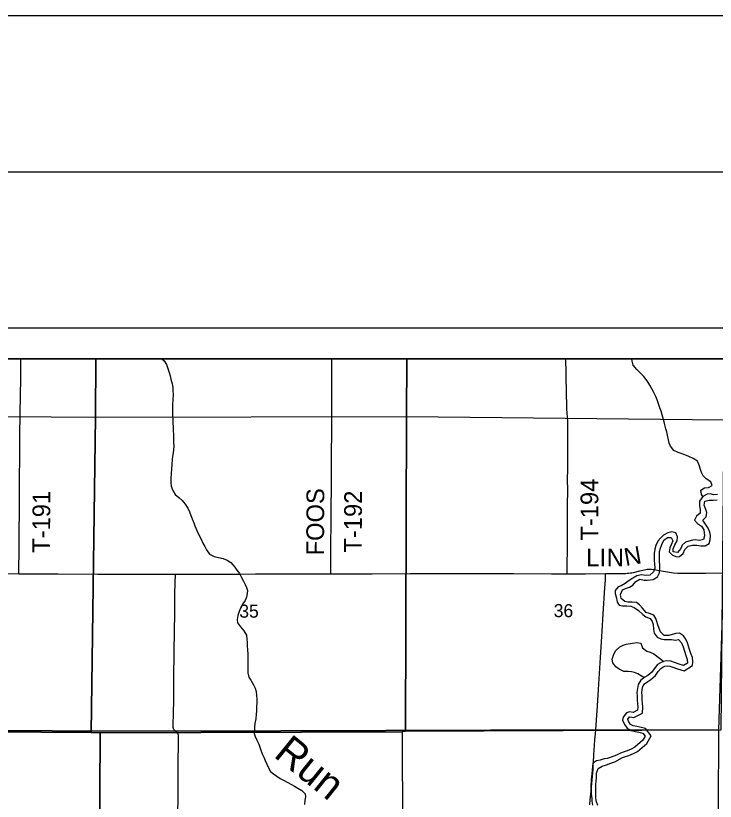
# Model space of a CAD drawing. Extents: x 0 to 45.9, y 0 to 22.
# Drawn here: x 3.224 to 5.466, y 19.483 to 22 of the extents above; entities that cross this region are included whole.
import ezdxf

# ---------------------------------------------------------------- set-up
doc = ezdxf.new("R2010")
doc.units = 0
for name, color, linetype in [('Default', 7, 'Continuous'), ('GM_X_County_Road', 7, 'Continuous'), ('GM_X_County_Road_Text', 7, 'Continuous'), ('GM_X_Major_River', 7, 'Continuous'), ('GM_X_Minor_River', 7, 'Continuous'), ('GM_X_Minor_River_Text', 7, 'Continuous'), ('GM_X_Section', 7, 'Continuous'), ('GM_X_Section_Text', 7, 'Continuous'), ('GM_X_Township_Road', 7, 'Continuous'), ('GM_X_Township_Road_Text', 7, 'Continuous'), ('SH_Cut_Line', 7, 'Continuous'), ('SH_Data', 7, 'Continuous'), ('SH_Text', 7, 'Continuous')]:
    doc.layers.add(name, color=color, linetype=linetype)

msp = doc.modelspace()

# ---------------------------------------------------------------- linework, layer by layer
at = {"layer": 'Default'}
for points in [[(5.5025, 20.9), (2.1, 20.9), (2.1, 19.7114), (2.15, 19.7113), (3.7367, 19.7072), (5.0826, 19.712), (5.4773, 19.7108), (5.4937, 20.2154)], [(3.4805, 20.9), (2.4813, 20.9), (2.4804, 20.7206), (3.4792, 20.7133)], [(4.477, 20.9), (3.4805, 20.9), (3.4792, 20.7133), (4.4764, 20.7161)], [(5.4943, 20.9), (4.477, 20.9), (4.4764, 20.7161), (5.4933, 20.7051)], [(2.1, 19.7114), (2.1, 14.1), (5.4538, 14.1), (5.4606, 15.6588), (5.4651, 16.7018), (5.4694, 17.7061), (5.4802, 18.3214), (5.4737, 18.7216), (5.4752, 19.0482), (5.4759, 19.2109), (5.4773, 19.7108), (5.0826, 19.712), (3.7367, 19.7072), (2.15, 19.7113)]]:
    msp.add_lwpolyline(points, close=True, dxfattribs=at)
at = {"layer": 'GM_X_County_Road'}
for points in [[(2.2656, 20.2142), (2.3, 20.2144), (2.3995, 20.2148), (2.4461, 20.2148), (2.5274, 20.2146), (2.617, 20.2142), (2.7134, 20.2139), (2.7506, 20.2139), (2.8874, 20.2128), (2.962, 20.2127), (3.0987, 20.2123), (3.2334, 20.2117)], [(5.1146, 20.2123), (5.1219, 20.2124), (5.1549, 20.2128), (5.171, 20.213), (5.1779, 20.213), (5.1838, 20.2134), (5.1894, 20.2138), (5.1946, 20.2143), (5.1986, 20.215), (5.204, 20.216), (5.2239, 20.2209), (5.2388, 20.2248), (5.2438, 20.2259), (5.2481, 20.2264), (5.253, 20.2266), (5.2573, 20.2264), (5.2622, 20.226), (5.2694, 20.2251), (5.2757, 20.2243), (5.2858, 20.2227), (5.2999, 20.2202), (5.3194, 20.2165), (5.3259, 20.2155), (5.3324, 20.2148), (5.3463, 20.2139), (5.3569, 20.2137), (5.4364, 20.214), (5.4929, 20.2148)], [(3.2334, 20.2117), (3.2572, 20.2116), (3.3598, 20.2112), (3.4872, 20.2108), (3.5866, 20.2106), (3.711, 20.2109), (3.7356, 20.2109)], [(3.7356, 20.2109), (3.8228, 20.2108), (3.944, 20.2108), (3.992, 20.2111), (4.1119, 20.2116), (4.2144, 20.2116), (4.2337, 20.2116)], [(4.2337, 20.2116), (4.2766, 20.2117), (4.3667, 20.212), (4.4879, 20.2121), (4.6246, 20.2122), (4.6837, 20.2122), (4.8205, 20.2121), (4.9416, 20.2119), (4.9918, 20.2119)], [(4.9918, 20.2119), (5.0504, 20.2119), (5.1146, 20.2123)], [(5.0828, 19.7114), (5.085, 19.7422), (5.0883, 19.7887), (5.0919, 19.8413), (5.0985, 19.9436), (5.1018, 19.9932), (5.1039, 20.0273), (5.1071, 20.0831), (5.1125, 20.1668), (5.1139, 20.1914), (5.1142, 20.1993), (5.1145, 20.2092), (5.1146, 20.2123)], [(5.0636, 19.4717), (5.0655, 19.4888), (5.0671, 19.5049), (5.0698, 19.5293), (5.0717, 19.5509), (5.0737, 19.5725), (5.0745, 19.583), (5.0748, 19.5898), (5.0752, 19.6), (5.0755, 19.6065), (5.077, 19.632), (5.0789, 19.6618), (5.0804, 19.6804), (5.0819, 19.6989), (5.0828, 19.7114)]]:
    msp.add_lwpolyline(points, dxfattribs=at)
at = {"layer": 'GM_X_Major_River'}
for points in [[(5.4738, 20.4657), (5.4613, 20.4648), (5.4496, 20.4681), (5.4401, 20.4668), (5.4263, 20.4591), (5.4158, 20.4449), (5.4151, 20.4305), (5.4175, 20.4171), (5.418, 20.4061), (5.4064, 20.3961), (5.4001, 20.3833), (5.4094, 20.3728), (5.4221, 20.3646), (5.429, 20.3523), (5.4311, 20.3424), (5.4312, 20.3329), (5.4283, 20.3216), (5.4154, 20.3188), (5.4022, 20.3202), (5.3927, 20.3193), (5.3809, 20.3165), (5.371, 20.3129), (5.3598, 20.3029), (5.3554, 20.2923), (5.3449, 20.28), (5.3317, 20.2822), (5.3312, 20.2921), (5.3367, 20.3041), (5.3438, 20.3172), (5.3452, 20.3297), (5.3402, 20.3428), (5.3274, 20.3457), (5.3137, 20.3429), (5.3007, 20.3356), (5.2906, 20.3259), (5.2825, 20.3159), (5.2754, 20.3023), (5.2721, 20.291), (5.2699, 20.2762), (5.27, 20.2664), (5.2705, 20.2538), (5.2715, 20.2439), (5.2723, 20.2302), (5.2683, 20.2178), (5.2567, 20.207), (5.2438, 20.2062), (5.2295, 20.2087), (5.215, 20.2052), (5.2016, 20.1975), (5.1901, 20.1906), (5.177, 20.1806), (5.1643, 20.1732), (5.1544, 20.1697), (5.1455, 20.1577), (5.1449, 20.1482), (5.1491, 20.1333), (5.1519, 20.1203), (5.1585, 20.1107), (5.169, 20.109), (5.1823, 20.1091), (5.1955, 20.108), (5.2064, 20.104), (5.2198, 20.0939), (5.2336, 20.081), (5.244, 20.074), (5.2572, 20.0684), (5.2641, 20.0584), (5.2666, 20.0488), (5.2678, 20.034), (5.2702, 20.0218), (5.2798, 20.009), (5.2921, 20.0031), (5.3023, 20.0014), (5.3125, 20.0011), (5.3262, 20.0016), (5.3386, 19.9995), (5.3485, 20.0012), (5.3581, 19.9899), (5.3635, 19.9777), (5.3674, 19.9632), (5.3717, 19.9498)], [(5.352, 20.0216), (5.3402, 20.0207), (5.328, 20.0168), (5.3173, 20.0136), (5.3026, 20.0143), (5.2903, 20.0255), (5.286, 20.0359), (5.2821, 20.0485), (5.2785, 20.0584), (5.2753, 20.068), (5.2687, 20.0788), (5.2549, 20.0848), (5.2451, 20.088), (5.2332, 20.1012), (5.2233, 20.112), (5.2132, 20.1198), (5.2, 20.1212), (5.1863, 20.1208), (5.1758, 20.1229), (5.165, 20.1322), (5.1622, 20.1456), (5.1686, 20.1599), (5.1789, 20.165), (5.1908, 20.1693), (5.2015, 20.1755), (5.2116, 20.1875), (5.2239, 20.1944), (5.2382, 20.1915), (5.248, 20.1909), (5.2575, 20.1918), (5.2674, 20.1939), (5.2812, 20.2023), (5.2879, 20.2151), (5.2889, 20.2276), (5.2881, 20.2402), (5.2875, 20.2504), (5.287, 20.2599), (5.2869, 20.2732), (5.2878, 20.2827), (5.2903, 20.2933), (5.2944, 20.3057), (5.3014, 20.3189), (5.3126, 20.3278), (5.3251, 20.3283), (5.3306, 20.3168), (5.3246, 20.3047), (5.3202, 20.2946), (5.3188, 20.2817), (5.3292, 20.2716), (5.3427, 20.2656), (5.3515, 20.2666), (5.363, 20.277), (5.369, 20.2898), (5.3798, 20.3002), (5.3931, 20.3033), (5.4068, 20.3034), (5.4203, 20.3008), (5.4343, 20.3009), (5.4466, 20.3086), (5.4499, 20.3207), (5.4506, 20.3348), (5.4485, 20.3447), (5.4439, 20.3581), (5.4351, 20.3708), (5.4259, 20.3835), (5.4367, 20.3947), (5.4393, 20.4079), (5.4364, 20.4175), (5.4311, 20.432), (5.4332, 20.4449), (5.4469, 20.4473), (5.4598, 20.4478), (5.4723, 20.4486)], [(5.393, 19.9182), (5.3944, 19.9307), (5.3931, 19.9429), (5.3881, 19.9563), (5.3834, 19.9689), (5.3799, 19.98), (5.3771, 19.9899), (5.3716, 20.0026), (5.3643, 20.0126), (5.352, 20.0216)], [(5.3717, 19.9498), (5.3759, 19.9372), (5.3768, 19.9257), (5.3638, 19.9177), (5.3502, 19.9217), (5.336, 19.9277), (5.3232, 19.9318), (5.3103, 19.9328), (5.3001, 19.9304), (5.2905, 19.9264), (5.2805, 19.9205), (5.2704, 19.9075), (5.263, 19.8966), (5.2503, 19.8858), (5.2407, 19.88), (5.2276, 19.8704), (5.2194, 19.8565), (5.2165, 19.844), (5.215, 19.8308), (5.2156, 19.8209), (5.2161, 19.8079), (5.2173, 19.7946), (5.2179, 19.7851), (5.2173, 19.7749), (5.2027, 19.7676), (5.1914, 19.7697), (5.1819, 19.7665), (5.171, 19.7527), (5.1693, 19.7428), (5.1754, 19.729), (5.1839, 19.7171), (5.1966, 19.7096), (5.2109, 19.7063), (5.2211, 19.7042), (5.2335, 19.7012), (5.2416, 19.6912), (5.2342, 19.6781), (5.2079, 19.6558), (5.1968, 19.65), (5.1835, 19.6442), (5.1739, 19.6413), (5.1625, 19.6374), (5.1491, 19.6305), (5.1323, 19.6244), (5.1197, 19.6201), (5.1102, 19.6184), (5.0973, 19.6145), (5.0855, 19.612), (5.074, 19.6047), (5.0722, 19.5945), (5.0712, 19.5823), (5.0702, 19.5713), (5.0689, 19.5607), (5.0679, 19.5513), (5.0675, 19.5296), (5.068, 19.5182), (5.0688, 19.5049), (5.0705, 19.4931), (5.0707, 19.4832), (5.0727, 19.4706)], [(5.1437, 19.6093), (5.1688, 19.6227), (5.1788, 19.6262), (5.1889, 19.6292), (5.2037, 19.6356), (5.2169, 19.6425), (5.2466, 19.6677), (5.2608, 19.6928), (5.2425, 19.7155), (5.2245, 19.7197), (5.2143, 19.7218), (5.2026, 19.7246), (5.1949, 19.7291), (5.1893, 19.7369), (5.1858, 19.7449), (5.186, 19.746), (5.1915, 19.7529), (5.1926, 19.7533), (5.2051, 19.751), (5.2326, 19.7648), (5.2338, 19.7851), (5.2332, 19.7958), (5.232, 19.809), (5.2315, 19.8216), (5.231, 19.8303), (5.2322, 19.8414), (5.2343, 19.8505), (5.2396, 19.8595), (5.2496, 19.8668), (5.2596, 19.8729), (5.2749, 19.8858), (5.2833, 19.8981), (5.2913, 19.9084), (5.2976, 19.9121), (5.305, 19.9152), (5.3116, 19.9168), (5.3201, 19.9161), (5.3305, 19.9128), (5.3449, 19.9067), (5.3661, 19.9004), (5.393, 19.9182)], [(5.0897, 19.4695), (5.0847, 19.4844), (5.0834, 19.497), (5.0833, 19.5069), (5.0831, 19.5164), (5.0833, 19.5263), (5.0835, 19.5357), (5.0841, 19.5483), (5.0851, 19.5581), (5.0858, 19.5729), (5.0906, 19.5876), (5.1041, 19.5957), (5.1174, 19.6), (5.1319, 19.605), (5.1437, 19.6093)]]:
    msp.add_lwpolyline(points, dxfattribs=at)
at = {"layer": 'GM_X_Minor_River'}
for points in [[(3.6925, 20.9), (3.6995, 20.8943), (3.7076, 20.8827), (3.7108, 20.8724), (3.7157, 20.8571), (3.7189, 20.846), (3.7213, 20.8353), (3.7252, 20.8201), (3.7272, 20.8094), (3.7278, 20.7999), (3.7282, 20.7855), (3.7272, 20.7703), (3.726, 20.7536), (3.7258, 20.7422), (3.726, 20.7312), (3.7261, 20.7205), (3.7272, 20.7027), (3.7274, 20.6932), (3.728, 20.6837), (3.7288, 20.6704), (3.729, 20.6582), (3.7295, 20.6468), (3.7299, 20.6327), (3.7301, 20.621), (3.7291, 20.6092), (3.7281, 20.5997), (3.7263, 20.588), (3.7254, 20.5778), (3.7243, 20.5634), (3.7228, 20.5471), (3.7218, 20.5334), (3.7211, 20.5186), (3.7208, 20.5034), (3.722, 20.492), (3.7271, 20.479), (3.7351, 20.4655), (3.7467, 20.4562), (3.7571, 20.4468), (3.767, 20.4352), (3.7755, 20.4218), (3.7809, 20.4099), (3.7852, 20.3988), (3.7891, 20.3877), (3.7942, 20.375), (3.7978, 20.3655), (3.8039, 20.3509), (3.8093, 20.3386)], [(5.4263, 20.4591), (5.4223, 20.4656), (5.4203, 20.4801), (5.4318, 20.4875), (5.4447, 20.4887), (5.4566, 20.4942), (5.4519, 20.506), (5.437, 20.5162), (5.4277, 20.5259), (5.4223, 20.5363), (5.4187, 20.5458), (5.4144, 20.56), (5.4094, 20.5726), (5.3956, 20.5809), (5.3813, 20.5873), (5.3689, 20.5928), (5.3573, 20.5969), (5.3471, 20.6001), (5.3336, 20.6065), (5.3222, 20.6208), (5.3186, 20.6307), (5.3166, 20.6414), (5.3135, 20.6555), (5.3107, 20.6662), (5.3079, 20.6765), (5.3047, 20.6891), (5.3023, 20.699), (5.2955, 20.7208), (5.2924, 20.7327), (5.2888, 20.743), (5.2842, 20.7568), (5.2795, 20.7686), (5.2752, 20.7801), (5.2694, 20.7928), (5.2632, 20.8047), (5.2567, 20.8162), (5.2475, 20.8301), (5.2376, 20.8443), (5.2246, 20.8571), (5.2149, 20.8661), (5.2035, 20.8804), (5.1996, 20.8934), (5.1985, 20.9)], [(3.8093, 20.3386), (3.8177, 20.3221), (3.8238, 20.3102), (3.8304, 20.2987), (3.8355, 20.2887), (3.8451, 20.2748), (3.86, 20.2666), (3.874, 20.264), (3.8883, 20.2607), (3.9015, 20.2554), (3.9138, 20.248), (3.926, 20.2333), (3.933, 20.2233), (3.9411, 20.2125), (3.9476, 20.1998), (3.9542, 20.1879), (3.9592, 20.1771), (3.9632, 20.1676), (3.9664, 20.158), (3.9658, 20.1481), (3.9633, 20.1372), (3.9593, 20.1262), (3.9507, 20.1139), (3.9448, 20.1011), (3.9404, 20.0906), (3.9356, 20.0777), (3.9334, 20.0653), (3.9351, 20.055), (3.9446, 20.0415), (3.9554, 20.0291), (3.963, 20.0153), (3.965, 20.0019), (3.9655, 19.9913), (3.9657, 19.9803), (3.9666, 19.9677), (3.9674, 19.954), (3.9675, 19.9415), (3.9676, 19.9271), (3.9674, 19.9168), (3.9679, 19.9058), (3.968, 19.894), (3.9712, 19.8803), (3.9778, 19.8706), (3.9858, 19.856), (3.9912, 19.8453), (3.9948, 19.835), (3.996, 19.8216), (3.9962, 19.811), (3.9964, 19.8004), (3.9957, 19.7848), (3.9954, 19.7715), (3.9948, 19.7617), (3.993, 19.7469), (3.9907, 19.7317), (3.9894, 19.72), (3.9888, 19.7098), (3.9886, 19.6999), (3.991, 19.69), (3.9964, 19.6785), (4.0026, 19.6658), (4.008, 19.6501), (4.0133, 19.6352), (4.0188, 19.6244), (4.0235, 19.6129), (4.0285, 19.6014), (4.0332, 19.5915), (4.0409, 19.5784), (4.0506, 19.5702), (4.0607, 19.5636), (4.0719, 19.5561), (4.0846, 19.549), (4.0943, 19.5435), (4.1074, 19.5364), (4.1175, 19.5316), (4.1276, 19.5246), (4.1411, 19.5174), (4.1518, 19.507), (4.1524, 19.4971), (4.151, 19.4865), (4.1496, 19.4724)], [(5.2392, 19.8789), (5.2317, 19.8821), (5.2182, 19.8915), (5.2073, 19.8955), (5.1975, 19.8976), (5.1877, 19.8982), (5.1726, 19.8989), (5.1576, 19.9064), (5.1479, 19.9138), (5.1379, 19.9262), (5.1359, 19.938), (5.1415, 19.9542), (5.1479, 19.9662), (5.1602, 19.9774), (5.1705, 19.9828), (5.1808, 19.9857), (5.2013, 19.989), (5.2143, 19.9918), (5.2271, 19.9893), (5.2332, 19.9747), (5.247, 19.9642), (5.2575, 19.9601), (5.2692, 19.9557), (5.3011, 19.9306)]]:
    msp.add_lwpolyline(points, dxfattribs=at)
at = {"layer": 'GM_X_Section'}
for points in [[(2.4804, 20.7206), (3.4792, 20.7133), (3.4656, 19.7033), (2.5108, 19.7095), (2.4582, 19.7121)], [(3.4792, 20.7133), (4.4764, 20.7161), (4.4734, 19.7064), (4.4624, 19.7057), (3.494, 19.7024), (3.4656, 19.7033)], [(4.4764, 20.7161), (5.4933, 20.7051), (5.4839, 19.711), (4.4734, 19.7064)], [(2.5108, 19.7095), (3.4656, 19.7033), (3.494, 19.7024), (3.4889, 18.7329), (2.5019, 18.7014)], [(3.494, 19.7024), (4.4624, 19.7057), (4.4658, 18.7509), (3.4889, 18.7329)]]:
    msp.add_lwpolyline(points, close=True, dxfattribs=at)
at = {"layer": 'GM_X_Township_Road'}
for points in [[(3.2334, 20.2117), (3.2335, 20.2148), (3.2343, 20.2967), (3.235, 20.3432), (3.2356, 20.4147), (3.2357, 20.4519), (3.236, 20.4861), (3.2361, 20.5296), (3.2367, 20.5731), (3.2374, 20.6476), (3.2384, 20.7315), (3.2391, 20.7781), (3.2399, 20.8433), (3.2403, 20.8774), (3.2406, 20.9)], [(4.2337, 20.2116), (4.2338, 20.2146), (4.234, 20.2212), (4.2341, 20.3051), (4.2344, 20.3734), (4.2349, 20.4262), (4.2358, 20.4852), (4.2359, 20.5163), (4.2361, 20.566), (4.2363, 20.6126), (4.2368, 20.6499), (4.237, 20.6716), (4.2372, 20.7493), (4.2373, 20.7927), (4.2372, 20.8145), (4.2374, 20.8393), (4.2368, 20.9)], [(4.9918, 20.2119), (4.9918, 20.2156), (4.9918, 20.2258), (4.9919, 20.2333), (4.9924, 20.2985), (4.9925, 20.3296), (4.9928, 20.398), (4.9928, 20.4135), (4.993, 20.4477), (4.9931, 20.4632), (4.9933, 20.4849), (4.9929, 20.5099), (4.9933, 20.551), (4.9937, 20.5922), (4.9938, 20.6134), (4.994, 20.6474), (4.994, 20.6557), (4.9936, 20.675), (4.9931, 20.6992), (4.9907, 20.7402), (4.99, 20.7582), (4.9892, 20.783), (4.9881, 20.8545), (4.9874, 20.9)], [(3.7296, 19.7151), (3.7292, 19.7161), (3.7284, 19.7191), (3.7281, 19.7222), (3.7281, 19.7253), (3.7295, 19.7657), (3.7304, 19.8061), (3.7309, 19.8527), (3.7309, 19.89), (3.7311, 19.9024), (3.7315, 19.9335), (3.7318, 19.9708), (3.7325, 20.0174), (3.7336, 20.095), (3.7341, 20.1417), (3.7349, 20.1883), (3.7354, 20.2038), (3.7356, 20.2109)], [(3.7369, 19.7066), (3.7344, 19.7085), (3.7322, 19.7107), (3.7304, 19.7132), (3.7296, 19.7151)], [(3.7417, 19.2433), (3.7418, 19.2625), (3.7425, 19.3247), (3.7431, 19.3837), (3.7436, 19.4272), (3.7444, 19.5111), (3.7449, 19.5981), (3.7446, 19.6136), (3.7455, 19.6633), (3.7456, 19.6882), (3.7453, 19.6944), (3.7447, 19.6975), (3.7435, 19.7003), (3.7417, 19.7027), (3.7394, 19.7048), (3.7369, 19.7066)]]:
    msp.add_lwpolyline(points, dxfattribs=at)
at = {"layer": 'SH_Cut_Line'}
for p, q in [((2, 21), (9, 21)), ((2.1, 20.9), (8.9, 20.9))]:
    msp.add_line(p, q, dxfattribs=at)
at = {"layer": 'SH_Data'}
msp.add_lwpolyline([(1.5, 21.5), (33.5, 21.5), (33.5, 0.5), (1.5, 0.5)], close=True, dxfattribs=at)
at = {"layer": 'SH_Text'}
msp.add_lwpolyline([(0, 0), (34, 0), (34, 22), (0, 22)], close=True, dxfattribs=at)
msp.add_lwpolyline([(8.9, 20.9), (2.1, 20.9)], dxfattribs=at)

# ---------------------------------------------------------------- texts
at = {"layer": 'GM_X_County_Road_Text'}
for s, rotation, p in [('L', 0, (5.0525, 20.2354)), ('I', 0, (5.095, 20.2354)), ('N', 0.0366, (5.1184, 20.2354)), ('N', 10.0321, (5.179, 20.2363))]:
    msp.add_text(s, height=0.0568, rotation=rotation, dxfattribs=at).set_placement(p)
at = {"layer": 'GM_X_Minor_River_Text'}
msp.add_text('Run', height=0.09472, rotation=321.0649, dxfattribs=at).set_placement((4.0475, 19.6274))
at = {"layer": 'GM_X_Section_Text'}
for s, p in [('35', (3.9405, 20.071)), ('36', (4.9484, 20.0727))]:
    msp.add_text(s, height=0.04186, rotation=0, dxfattribs=at).set_placement(p)
at = {"layer": 'GM_X_Township_Road_Text'}
for s, rotation, p in [('T-194', 90, (5.0912, 20.318)), ('T-191', 89.7193, (3.3337, 20.2788)), ('FOOS', 89.732, (4.2118, 20.2705)), ('T-192', 89.7216, (4.3328, 20.2796))]:
    msp.add_text(s, height=0.05682, rotation=rotation, dxfattribs=at).set_placement(p)

doc.saveas('drawing.dxf')
